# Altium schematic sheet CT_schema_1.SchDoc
size 463 x 258 mm
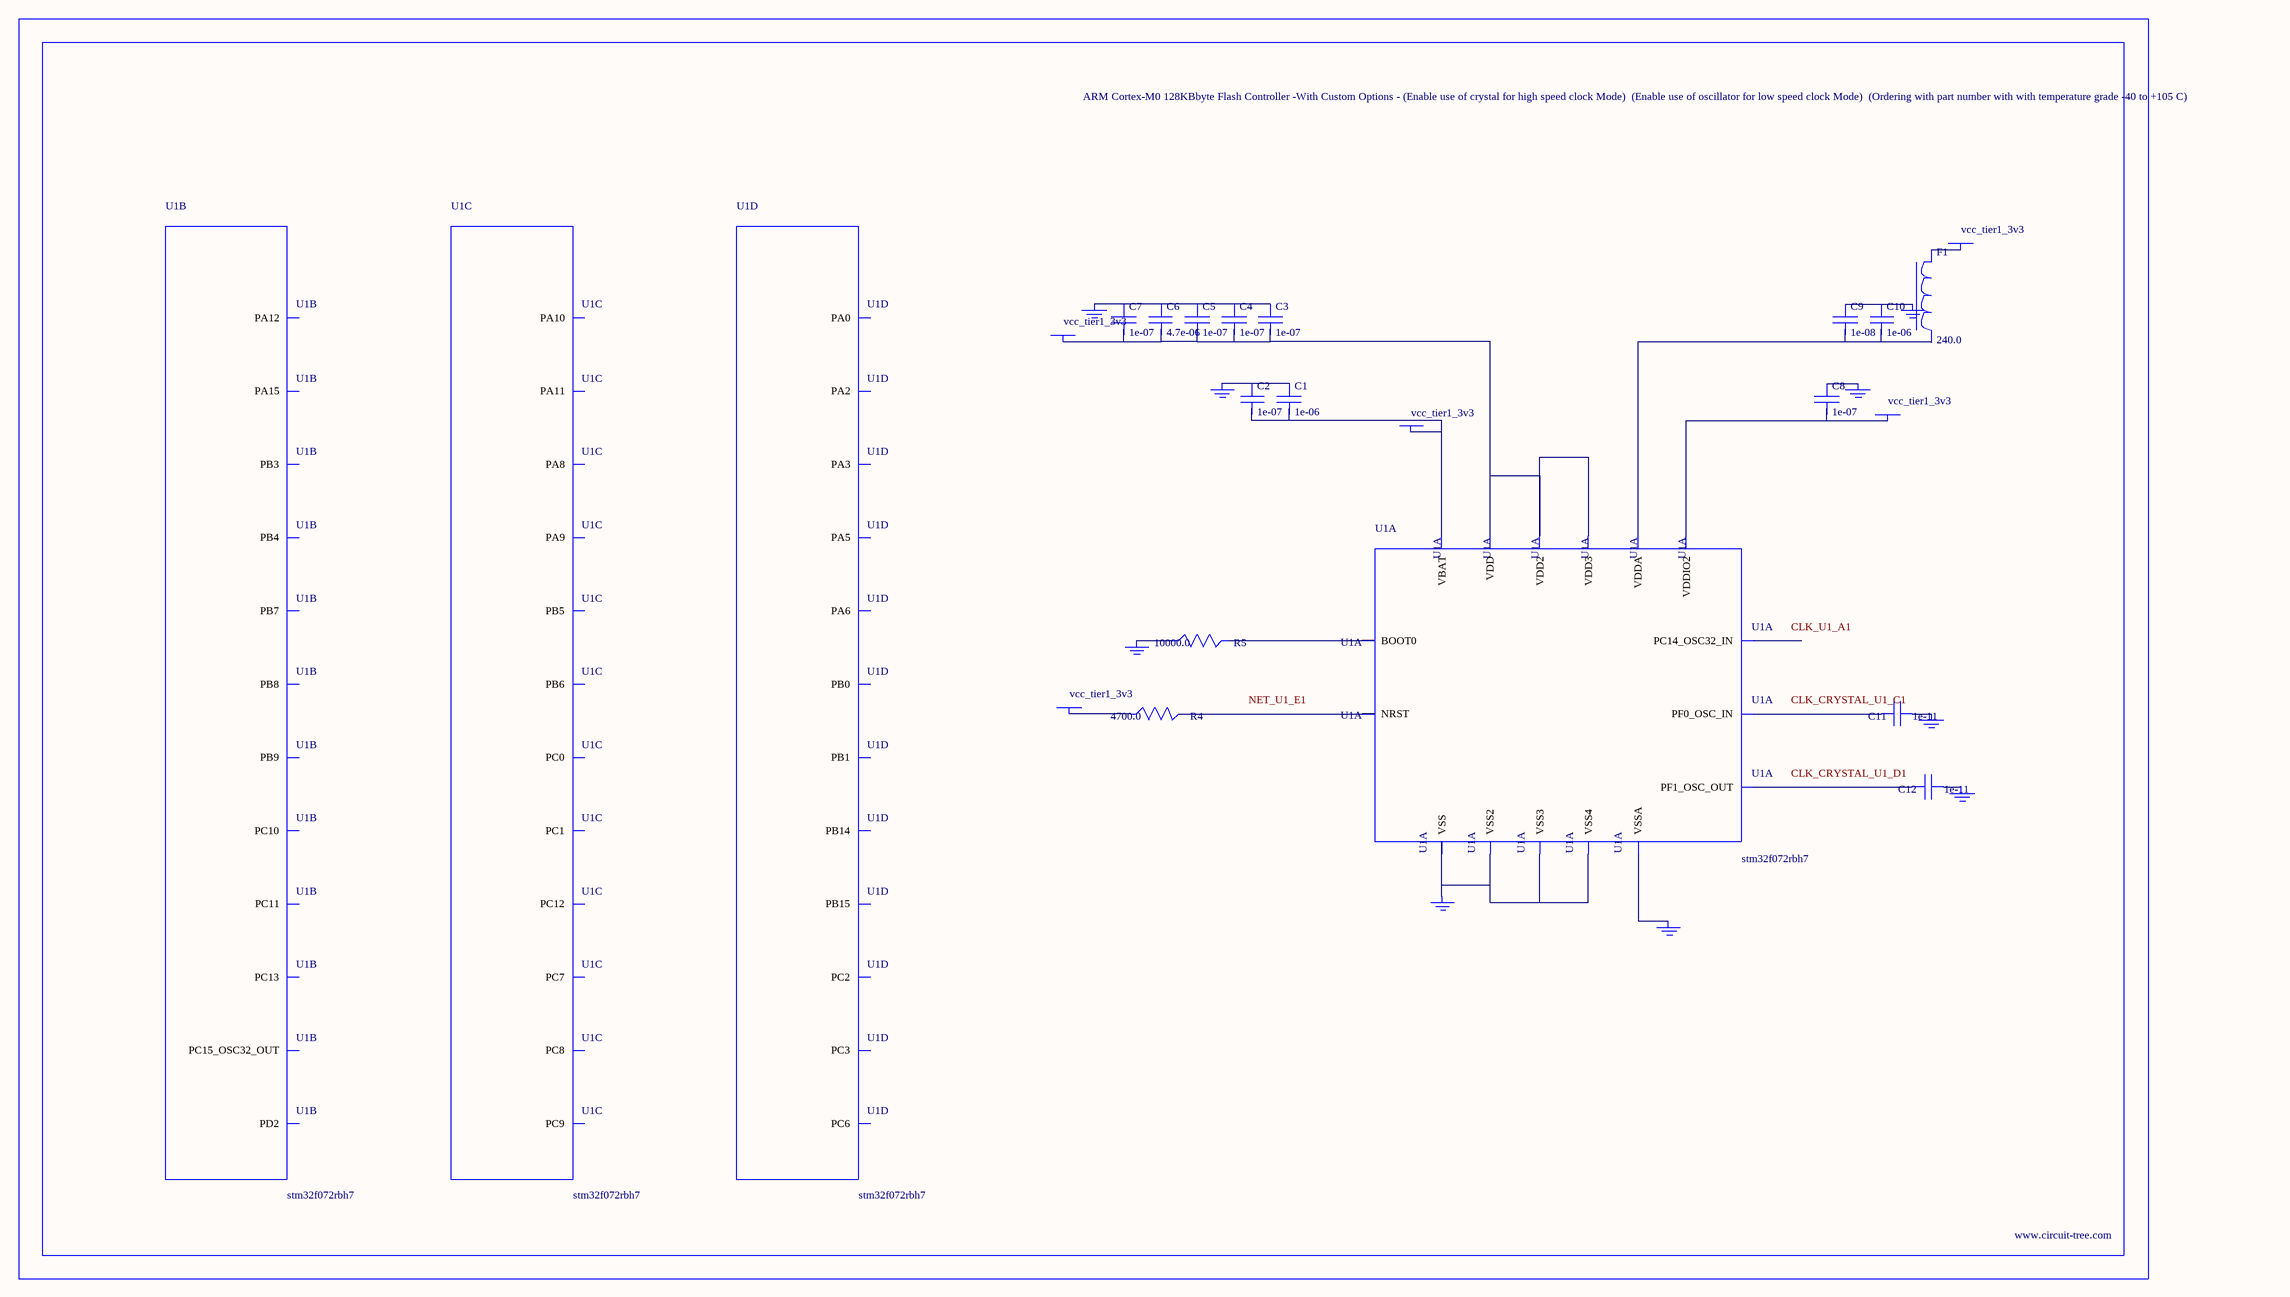
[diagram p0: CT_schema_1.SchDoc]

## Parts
BORDER0  (no value)
C1  1e-06  [C0603]
C2  1e-07  [C0603]
C3  1e-07  [C0603]
C4  1e-07  [C0603]
C5  1e-07  [C0603]
C6  4.7e-06  [C0603]
C7  1e-07  [C0603]
C8  1e-07  [C0603]
C9  1e-08  [C0603]
C10  1e-06  [C0603]
C11  1e-11  [C0402]
C12  1e-11  [C0402]
F1  240.0  [L0603]
GND_INSTANCE_0_0  (no value)
GND_INSTANCE_0_1  (no value)
GND_INSTANCE_0_2  (no value)
GND_INSTANCE_0_3  (no value)
GND_INSTANCE_0_4  (no value)
GND_INSTANCE_0_5  (no value)
GND_INSTANCE_0_6  (no value)
GND_INSTANCE_0_7  (no value)
GND_INSTANCE_0_8  (no value)
POWER_INSTANCE_0_0  vcc_tier1_3v3
POWER_INSTANCE_0_1  vcc_tier1_3v3
POWER_INSTANCE_0_2  vcc_tier1_3v3
POWER_INSTANCE_0_3  vcc_tier1_3v3
POWER_INSTANCE_0_4  vcc_tier1_3v3
R4  4700.0  [R0603]
R5  10000.0  [R0603]
U1  stm32f072rbh7  [UFBGA64]  (parts A,B,C,D of 5)

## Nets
NetC1_1: C1.1 C2.1 GND_INSTANCE_0_0.0(GND)
NetC1_2: C1.2 C2.2 POWER_INSTANCE_0_0.0(PWR) U1.B2(VBAT)
NetC3_1: C3.1 C4.1 C5.1 C6.1 C7.1 GND_INSTANCE_0_2.0(GND)
NetC3_2: C3.2 C4.2 C5.2 C6.2 C7.2 POWER_INSTANCE_0_2.0(PWR) U1.D2(VDD) U1.E4(VDD2) U1.E5(VDD3)
NetC8_1: C8.1 GND_INSTANCE_0_3.0(GND)
NetC8_2: C8.2 POWER_INSTANCE_0_3.0(PWR) U1.E6(VDDIO2)
NetC9_1: C9.1 C10.1 GND_INSTANCE_0_1.0(GND)
NetC9_2: C9.2 C10.2 U1.H1(VDDA)
NetC11_1: C11.1 GND_INSTANCE_0_5.0(GND)
NetC11_2: C11.2 U1.C1(PF0_OSC_IN)
NetC12_1: C12.1 GND_INSTANCE_0_6.0(GND)
NetC12_2: C12.2 U1.D1(PF1_OSC_OUT)
NetF1_1: F1.1 POWER_INSTANCE_0_1.0(PWR)
NetGND_INSTANCE_0_4_0: GND_INSTANCE_0_4.0(GND) R5.1
NetGND_INSTANCE_0_7_0: GND_INSTANCE_0_7.0(GND) U1.F1(VSSA)
NetGND_INSTANCE_0_8_0: GND_INSTANCE_0_8.0(GND) U1.C2(VSS) U1.D4(VSS2) U1.D5(VSS3) U1.D6(VSS4)
NetPOWER_INSTANCE_0_4_0: POWER_INSTANCE_0_4.0(PWR) R4.1
NetR4_2: R4.2 U1.E1(NRST)
NetR5_2: R5.2 U1.B4(BOOT0)

Not connected (* = marked no-connect by the designer): F1 2; U1 A1(PC14_OSC32_IN) A2(PC13) A3(PB9) A4(PB4) A5(PB3) A6(PA15) B1(PC15_OSC32_OUT) B3(PB8) B5(PD2) B6(PC11) B7(PC10) B8(PA12) C3(PB7) C4(PB5) C5(PC12) C6(PA10) C7(PA9) C8(PA11) D3(PB6) D7(PA8) D8(PC9) E2(PC1) E3(PC0) E7(PC7) E8(PC8) F2(PC2) F3(PA2) F4(PA5) F5(PB0) F6(PC6) F7(PB15) F8(PB14) G1(PC3) G2(PA0) G3(PA3) G4(PA6) G5(PB1)

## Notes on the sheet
- Labels drawn without touching a wire or pin: CLK_CRYSTAL_U1_C1, CLK_CRYSTAL_U1_D1, CLK_U1_A1, NET_U1_E1

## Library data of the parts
BORDER0 = BORDER_PAGE0
C1 C10 = C0603C105K3RACTU
C2-C5 C7 C8 = 06035C104K4Z2A
C6 = GRM188R6YA475KE15D
C9 = 06035C103K4Z2A
C11 C12 = C0402C100K3GACTU
F1 = Z0603C241ASMST
GND_INSTANCE_0_0-GND_INSTANCE_0_8 = GND
POWER_INSTANCE_0_0-POWER_INSTANCE_0_4 = PWR
R4 = RC0603JR-074K7L
R5 = RC0603JR-0710KL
